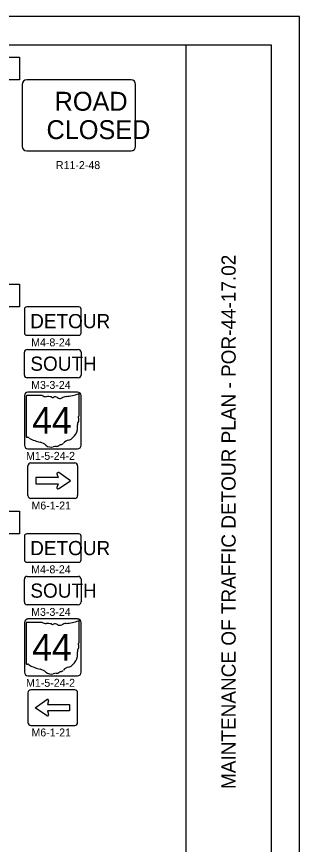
# Model space of a CAD drawing. Extents: x 0 to 34, y 0 to 22.
# Drawn here: x 29.01 to 34, y 7.41 to 22 of the extents above; entities that cross this region are included whole.
import ezdxf

# ---------------------------------------------------------------- set-up
doc = ezdxf.new("R2010")
doc.units = 0
for name, color, linetype in [('SH_Border', 7, 'Continuous'), ('SH_Cut_Line', 7, 'Continuous'), ('SH_Data', 7, 'Continuous'), ('SH_Text', 7, 'Continuous'), ('SN_P_Signs', 7, 'Continuous'), ('SN_P_Text', 7, 'Continuous')]:
    doc.layers.add(name, color=color, linetype=linetype)

msp = doc.modelspace()

# ---------------------------------------------------------------- linework, layer by layer
at = {"layer": 'SH_Border'}
msp.add_line((32, 0.5), (32, 21.5), dxfattribs=at)
msp.add_lwpolyline([(1.5, 21.5), (33.5, 21.5), (33.5, 0.5), (1.5, 0.5)], close=True, dxfattribs=at)
at = {"layer": 'SH_Cut_Line'}
msp.add_lwpolyline([(0, 0), (34, 0), (34, 22), (0, 22)], close=True, dxfattribs=at)
at = {"layer": 'SH_Text'}
for points in [[(28.701, 21.282), (29.064, 21.282), (29.064, 20.882), (28.701, 20.882)], [(28.701, 17.282), (29.064, 17.282), (29.064, 16.882), (28.701, 16.882)], [(28.701, 13.282), (29.064, 13.282), (29.064, 12.882), (28.701, 12.882)]]:
    msp.add_lwpolyline(points, close=True, dxfattribs=at)
at = {"layer": 'SN_P_Signs'}
for p, q in [((29.149, 15.682), (29.149, 16.082)), ((29.199, 16.132), (30.099, 16.132)), ((30.149, 16.082), (30.149, 15.682)), ((30.099, 15.632), (29.199, 15.632)), ((29.464, 15.322), (29.189, 15.322)), ((30.117, 14.967), (30.117, 15.34)), ((29.18, 15.31), (29.18, 14.598)), ((30.117, 14.968), (30.117, 14.967)), ((29.212, 13.557), (29.212, 14.082)), ((29.262, 14.132), (30.037, 14.132)), ((30.087, 14.082), (30.087, 13.557)), ((29.743, 13.874), (29.352, 13.874)), ((29.352, 13.874), (29.352, 13.765)), ((29.723, 13.938), (29.743, 13.874)), ((29.962, 13.819), (29.755, 13.962)), ((29.352, 13.765), (29.743, 13.765)), ((29.743, 13.765), (29.723, 13.701)), ((29.758, 13.68), (29.962, 13.819)), ((30.037, 13.507), (29.262, 13.507)), ((29.199, 12.132), (30.099, 12.132)), ((29.149, 11.682), (29.149, 12.082)), ((30.149, 12.082), (30.149, 11.682)), ((30.099, 11.632), (29.199, 11.632)), ((29.18, 11.31), (29.18, 10.598)), ((29.464, 11.322), (29.189, 11.322)), ((30.117, 10.967), (30.117, 11.34)), ((30.117, 10.968), (30.117, 10.967)), ((29.212, 10.082), (29.212, 9.557)), ((30.037, 10.132), (29.262, 10.132)), ((30.037, 10.132), (30.037, 10.132)), ((30.087, 9.557), (30.087, 10.082)), ((29.337, 9.819), (29.544, 9.962)), ((29.575, 9.938), (29.556, 9.874)), ((29.541, 9.68), (29.337, 9.819)), ((29.556, 9.874), (29.946, 9.874)), ((29.946, 9.874), (29.946, 9.765)), ((29.946, 9.765), (29.556, 9.765)), ((29.556, 9.765), (29.575, 9.701)), ((29.262, 9.507), (30.037, 9.507))]:
    msp.add_line(p, q, dxfattribs=at)
for points in [[(31.033, 20.882), (29.189, 20.882)], [(29.111, 20.804), (29.111, 19.71)], [(31.111, 19.71), (31.111, 20.804)], [(29.189, 19.632), (31.033, 19.632)], [(29.149, 16.842), (29.149, 16.422)], [(30.109, 16.882), (29.189, 16.882)], [(30.149, 16.422), (30.149, 16.842)], [(29.189, 16.382), (30.109, 16.382)], [(30.087, 15.382), (29.212, 15.382)], [(29.149, 15.319), (29.149, 14.444)], [(30.149, 14.444), (30.149, 15.319)], [(29.212, 14.382), (30.087, 14.382)], [(29.149, 12.842), (29.149, 12.422)], [(30.109, 12.882), (29.189, 12.882)], [(30.149, 12.422), (30.149, 12.842)], [(29.189, 12.382), (30.109, 12.382)], [(30.087, 11.382), (29.212, 11.382)], [(29.149, 11.319), (29.149, 10.444)], [(30.149, 10.444), (30.149, 11.319)], [(29.212, 10.382), (30.087, 10.382)]]:
    msp.add_lwpolyline(points, dxfattribs=at)
for centre, radius, start, end in [((29.189, 20.804), 0.0783, 90, 180), ((31.033, 20.804), 0.0783, 0, 90), ((29.189, 19.71), 0.0783, 180, 270), ((31.033, 19.71), 0.0783, 270, 0), ((29.189, 16.842), 0.04, 90, 180), ((30.109, 16.842), 0.04, 0, 90), ((29.189, 16.422), 0.04, 180, 270), ((30.109, 16.422), 0.04, 270, 0), ((29.199, 16.082), 0.05, 90, 180), ((30.099, 16.082), 0.05, 0, 90), ((29.199, 15.682), 0.05, 180, 270), ((30.099, 15.682), 0.05, 270, 0), ((29.212, 15.319), 0.0625, 90, 180), ((29.191, 15.311), 0.0109, 98.1301, 188.1301), ((29.529, 15.405), 0.105, 231.6195, 271.1119), ((29.783, 16.292), 0.994, 275.8445, 288.9065), ((30.087, 15.319), 0.0625, 0, 90), ((30.107, 15.341), 0.0104, 351.8621, 97.738), ((29.564, 14.923), 0.378, 80.4867, 94.9883), ((29.65, 15.315), 0.0304, 219.7921, 297.1024), ((29.694, 15.233), 0.0632, 54.4667, 119.1411), ((29.776, 15.346), 0.076, 233.8562, 294.8282), ((29.91, 15.105), 0.2, 97.3462, 120.7689), ((30.115, 14.94), 0.0162, 107.944, 210.337), ((30.012, 14.893), 0.097, 340.033, 23.6496), ((30.106, 14.966), 0.0112, 289.6038, 7.7341), ((29.839, 14.764), 0.249, 292.3089, 8.9858), ((30.155, 14.812), 0.0705, 136.8065, 186.9296), ((29.191, 14.597), 0.011, 171.9584, 258.3066), ((29.192, 14.669), 0.0836, 267.339, 280.6039), ((29.209, 14.557), 0.0302, 29.7484, 93.2717), ((29.59, 15.196), 0.718, 240.4129, 257.1985), ((29.376, 14.279), 0.225, 47.1842, 75.836), ((29.712, 14.5), 0.0759, 268.777, 315.5493), ((29.781, 14.431), 0.0214, 65.7517, 132.6484), ((29.771, 14.529), 0.0803, 282.8732, 323.2771), ((29.944, 14.398), 0.136, 94.4031, 142.5768), ((29.212, 14.444), 0.0625, 180, 270), ((29.619, 14.554), 0.143, 230.7004, 286.2918), ((29.701, 14.308), 0.117, 85.6951, 111.2099), ((30.087, 14.444), 0.0625, 270, 0), ((29.262, 14.082), 0.05, 90, 180), ((30.037, 14.082), 0.05, 0, 90), ((29.743, 13.944), 0.0209, 55.4112, 197.2046), ((29.743, 13.694), 0.0209, 162.7954, 315.0096), ((29.262, 13.557), 0.05, 180, 270), ((30.037, 13.557), 0.05, 270, 360), ((29.189, 12.842), 0.04, 90, 180), ((30.109, 12.842), 0.04, 0, 90), ((29.189, 12.422), 0.04, 180, 270), ((30.109, 12.422), 0.04, 270, 0), ((29.199, 12.082), 0.05, 90, 180), ((30.099, 12.082), 0.05, 0, 90), ((29.199, 11.682), 0.05, 180, 270), ((30.099, 11.682), 0.05, 270, 0), ((29.212, 11.319), 0.0625, 90, 180), ((30.087, 11.319), 0.0625, 0, 90), ((29.191, 11.311), 0.0109, 98.1301, 188.1301), ((29.529, 11.405), 0.105, 231.6195, 271.1119), ((29.564, 10.923), 0.378, 80.4867, 94.9883), ((29.65, 11.315), 0.0304, 219.7921, 297.1024), ((29.694, 11.233), 0.0632, 54.4667, 119.1411), ((29.776, 11.346), 0.076, 233.8562, 294.8282), ((29.91, 11.105), 0.2, 97.3462, 120.7689), ((29.783, 12.292), 0.994, 275.8445, 288.9065), ((30.107, 11.341), 0.0104, 351.8621, 97.738), ((30.115, 10.94), 0.0162, 107.944, 210.337), ((30.106, 10.966), 0.0112, 289.6038, 7.7341), ((29.839, 10.764), 0.249, 292.3089, 8.9858), ((30.155, 10.812), 0.0705, 136.8065, 186.9296), ((30.012, 10.893), 0.097, 340.033, 23.6496), ((29.191, 10.597), 0.011, 171.9584, 258.3066), ((29.192, 10.669), 0.0836, 267.339, 280.6039), ((29.209, 10.557), 0.0302, 29.7484, 93.2717), ((29.59, 11.196), 0.718, 240.4129, 257.1985), ((29.944, 10.398), 0.136, 94.4031, 142.5768), ((29.212, 10.444), 0.0625, 180, 270), ((29.376, 10.279), 0.225, 47.1842, 75.836), ((29.619, 10.554), 0.143, 230.7004, 286.2918), ((29.701, 10.308), 0.117, 85.6951, 111.2099), ((29.712, 10.5), 0.0759, 268.777, 315.5493), ((29.781, 10.431), 0.0214, 65.7517, 132.6484), ((29.771, 10.529), 0.0803, 282.8732, 323.2771), ((30.087, 10.444), 0.0625, 270, 0), ((29.262, 10.082), 0.05, 90, 180), ((30.037, 10.082), 0.05, 0, 90), ((29.556, 9.944), 0.0209, 342.7954, 124.5888), ((29.556, 9.694), 0.0209, 224.9904, 17.2046), ((29.262, 9.557), 0.05, 180, 270), ((30.037, 9.557), 0.05, 270, 0)]:
    msp.add_arc(centre, radius, start, end, dxfattribs=at)

# ---------------------------------------------------------------- texts
at = {"layer": 'SH_Data'}
msp.add_text('MAINTENANCE OF TRAFFIC DETOUR PLAN - POR-44-17.02', height=0.25, rotation=90, dxfattribs=at).set_placement((32.875, 8.385))
at = {"layer": 'SN_P_Signs'}
for s, height, p in [('ROAD', 0.3333, (29.682, 20.34)), ('CLOSED', 0.3333, (29.539, 19.84)), ('DETOUR', 0.25, (29.251, 16.507)), ('SOUTH', 0.25, (29.254, 15.757)), ('44', 0.4688, (29.286, 14.648)), ('DETOUR', 0.25, (29.251, 12.507)), ('SOUTH', 0.25, (29.254, 11.757)), ('44', 0.4688, (29.286, 10.648))]:
    msp.add_text(s, height=height, dxfattribs=at).set_placement(p)
at = {"layer": 'SN_P_Text'}
for s, p in [('R11-2-48', (29.705, 19.312)), ('M4-8-24', (29.268, 16.187)), ('M3-3-24', (29.268, 15.437)), ('M1-5-24-2', (29.178, 14.187)), ('M6-1-21', (29.274, 13.312)), ('M4-8-24', (29.268, 12.187)), ('M3-3-24', (29.268, 11.437)), ('M1-5-24-2', (29.178, 10.187)), ('M6-1-21', (29.274, 9.312))]:
    msp.add_text(s, height=0.14, dxfattribs=at).set_placement(p)

doc.saveas('drawing.dxf')
